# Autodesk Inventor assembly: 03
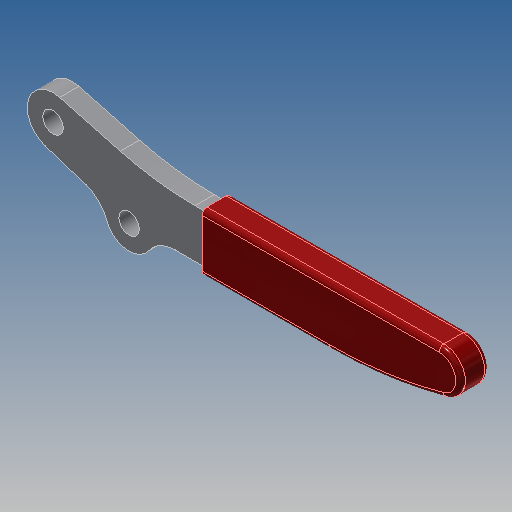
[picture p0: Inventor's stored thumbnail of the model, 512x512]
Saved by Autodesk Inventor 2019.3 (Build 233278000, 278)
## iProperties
Created: 2011-05
Part Number: 03
Material: Ogólny
Document SubType Name: Assembly
Designer: CADENGINEERING4
Author: CADENGINEERING4
Revision Number: ÈÎºÎ
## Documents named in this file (3)
- E:\STRONA\Horizontal toggle clamp\CH-202-FL\03.iam
- E:\STRONA\Horizontal toggle clamp\CH-202-FL\203-F-03-02.ipt
- E:\STRONA\Horizontal toggle clamp\CH-202-FL\203-F-03.ipt
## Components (2 placed, 2 different names)
1. 203-F-03-02_15
2. 203-F-03_16
